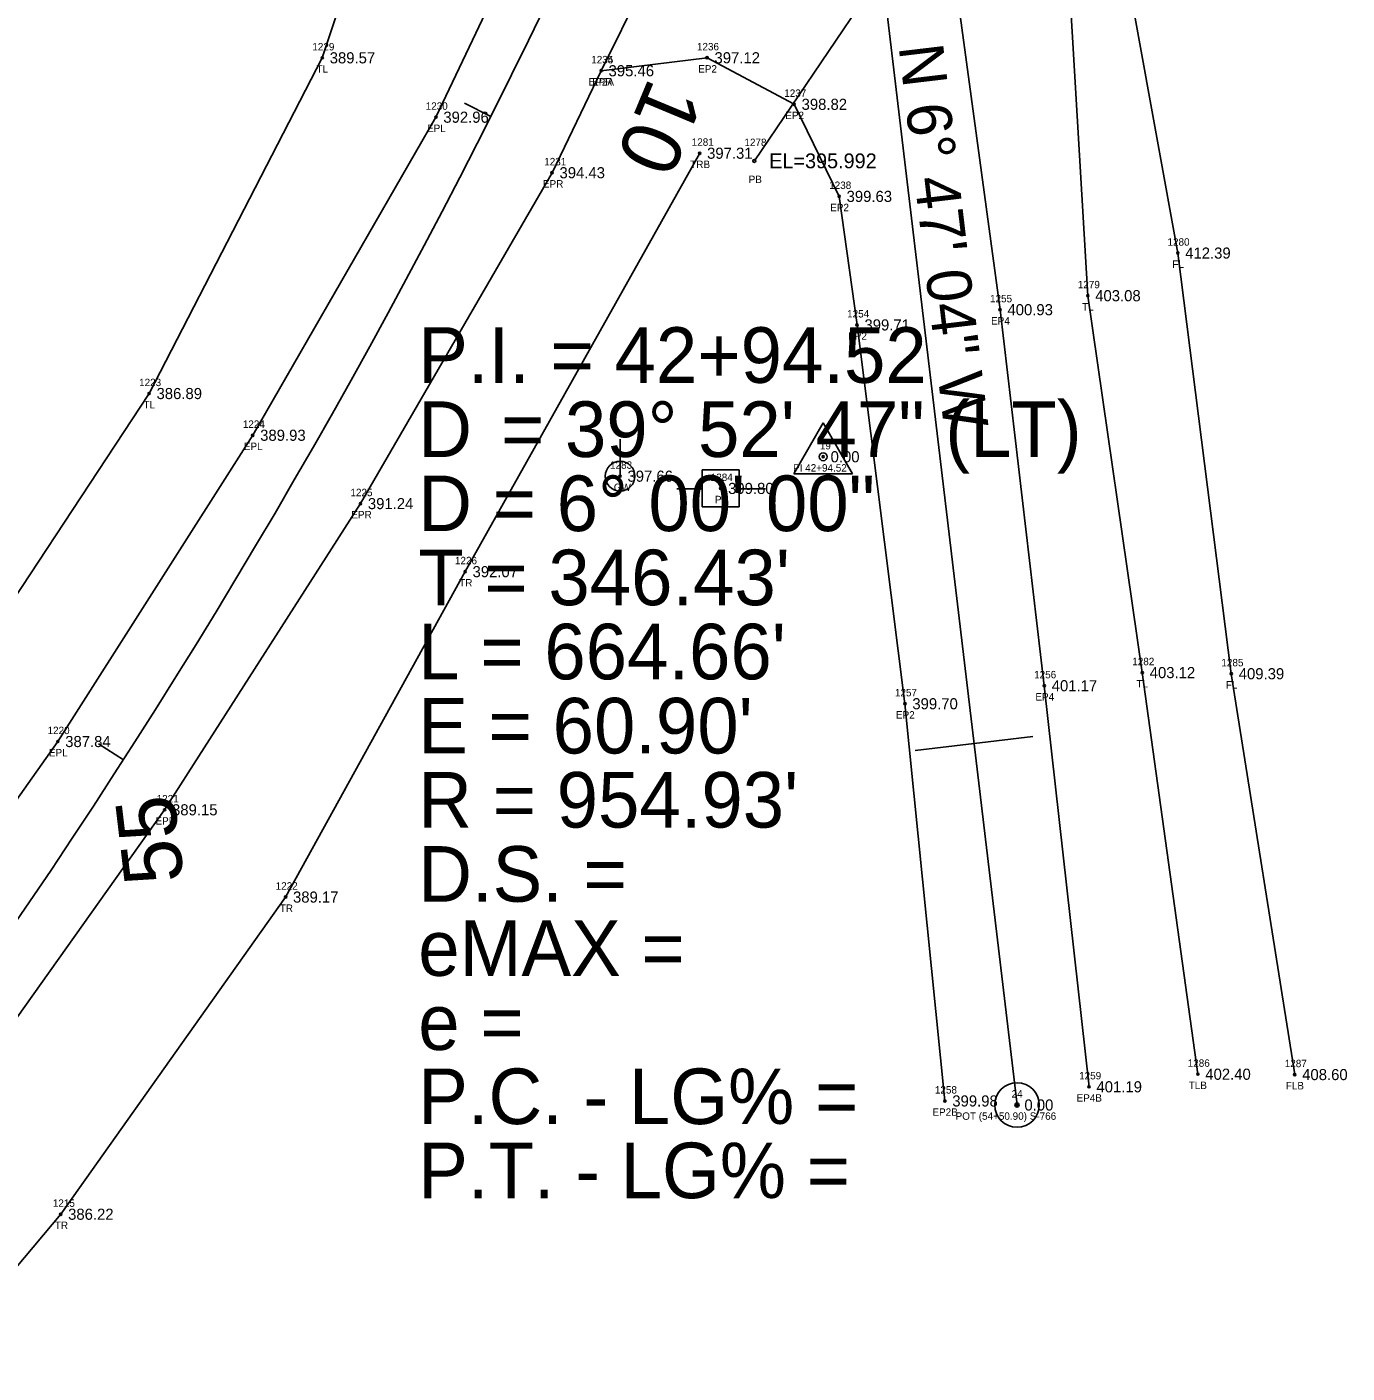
# Model space of a CAD drawing. Extents: x 2116015 to 2118228, y 979206 to 981145.
# Drawn here: x 2117886.2 to 2118064.3, y 980605.4 to 980787 of the extents above; entities that cross this region are included whole.
import ezdxf

# ---------------------------------------------------------------- set-up
doc = ezdxf.new("R2010")
doc.units = 0
for name, color, linetype in [('RD_EX_DR_Pipe', 7, 'Continuous'), ('RD_EX_DR_Pipe_txCode', 7, 'Continuous'), ('RD_EX_Fence_Other', 7, 'Continuous'), ('RD_EX_Fence_Other_txCode', 7, 'Continuous'), ('RD_EX_Road', 7, 'Continuous'), ('RD_EX_Road_txCode', 7, 'Continuous'), ('RD_EX_TX_Fence_Other_ELEV', 7, 'Continuous'), ('RD_EX_TX_Road_ELEV', 7, 'Continuous'), ('RD_EX_TX_UT_ELEV', 7, 'Continuous'), ('RD_EX_TX_VEG_ELEV', 7, 'Continuous'), ('RD_EX_UT', 7, 'Continuous'), ('RD_EX_UT_txCode', 7, 'Continuous'), ('RD_EX_VEG', 7, 'Continuous'), ('RD_EX_VEG_txCode', 7, 'Continuous'), ('RD_HC_Cl', 7, 'Continuous'), ('RD_HC_Data', 7, 'Continuous'), ('RD_HC_Data_Tic', 7, 'Continuous'), ('RD_HC_Survey_ELEV', 7, 'Continuous'), ('RD_HC_TX_Sta50', 7, 'Continuous'), ('RD_HC_txCode', 7, 'Continuous'), ('RD_SMD_Locator', 7, 'Continuous'), ('RD_TX_Pipe_ElevEX', 7, 'Continuous')]:
    doc.layers.add(name, color=color, linetype=linetype)

msp = doc.modelspace()

# ---------------------------------------------------------------- linework, layer by layer
at = {"layer": 'RD_EX_DR_Pipe'}
msp.add_line((2118018.48, 980819.47), (2117984.34, 980768.95), dxfattribs=at)
at = {"layer": 'RD_EX_Fence_Other'}
msp.add_lwpolyline([(2118035.7, 980855.33), (2118030.12, 980818.94), (2118041.46, 980756.51), (2118048.68, 980699.76), (2118057.24, 980645.68)], dxfattribs=at)
at = {"layer": 'RD_EX_Road'}
for points in [[(2117394.63, 980185.41), (2117388.45, 980192.75), (2117469.76, 980266.25), (2117487.02, 980282.1), (2117515.02, 980307.24), (2117543.53, 980333.04), (2117617.72, 980400.8), (2117691.88, 980468.07), (2117729.57, 980501.96), (2117798.93, 980572.83), (2117831.02, 980611), (2117861.69, 980650.07), (2117890.37, 980690.61), (2117916.67, 980731.93), (2117941.38, 980774.84), (2117963.75, 980821.95), (2117981.56, 980869.78), (2117996.2, 980917.73), (2118008.9, 980966.42), (2118019.55, 981015.46)], [(2117394.63, 980185.41), (2117401.85, 980177.36), (2117480.62, 980253.04), (2117556.27, 980319.95), (2117629.74, 980387.35), (2117703.2, 980454.29), (2117741.39, 980488.9), (2117777.53, 980523.58), (2117812.39, 980561.12), (2117844.66, 980599.64), (2117874.87, 980639.35), (2117904.78, 980681.4), (2117931.2, 980722.71), (2117957.05, 980767.35), (2117963.67, 980781.11), (2117980.28, 980814.62), (2117997.91, 980861.19), (2118015.62, 980912.37), (2118026.01, 980961.08), (2118037.02, 981011.88)], [(2118015.62, 980912.37), (2118010.99, 980870.98), (2118009.51, 980838.78), (2118009.44, 980820.82), (2118010.46, 980800.84), (2118017.48, 980748.87), (2118023.45, 980698.14), (2118029.49, 980644.03)], [(2117963.67, 980781.11), (2117977.96, 980782.86), (2117989.71, 980776.58), (2117995.78, 980764.16), (2117998.19, 980746.82), (2118004.65, 980695.71), (2118010.04, 980642.12)]]:
    msp.add_lwpolyline(points, dxfattribs=at)
at = {"layer": 'RD_EX_UT'}
for p, q in [((2117966.22, 980726.41), (2117966.22, 980731.41)), ((2117982.29, 980727.27), (2117977.29, 980727.27)), ((2117977.29, 980727.27), (2117977.29, 980722.27)), ((2117982.29, 980722.27), (2117982.29, 980727.27)), ((2117973.86, 980724.71), (2117977.33, 980724.71)), ((2117982.22, 980724.71), (2117985.86, 980724.71)), ((2117977.29, 980722.27), (2117982.29, 980722.27))]:
    msp.add_line(p, q, dxfattribs=at)
msp.add_circle((2117966.22, 980726.41), 2, dxfattribs=at)
at = {"layer": 'RD_EX_VEG'}
for points in [[(2117785.53, 980582.83), (2117819.37, 980618.82), (2117850.9, 980657.73), (2117876.27, 980697.46), (2117902.69, 980737.56), (2117926.05, 980782.85), (2117940.93, 980827.63), (2117963.69, 980874.19), (2117983.46, 980925.01), (2117981.09, 980973.08), (2118009.42, 981019.14)], [(2118029.75, 980856.49), (2118024.76, 980827.37), (2118029.32, 980750.76), (2118036.67, 980699.91), (2118044.17, 980645.73)], [(2117858.05, 980587.85), (2117890.76, 980626.84), (2117921.1, 980669.63), (2117945.32, 980713.53), (2117976.96, 980769.98)]]:
    msp.add_lwpolyline(points, dxfattribs=at)
at = {"layer": 'RD_HC_Cl'}
msp.add_line((2118019.77, 980641.58), (2117992.06, 980874.54), dxfattribs=at)
msp.add_arc((2117095.97, 981204.56), 954.93, 312.14821, 352.02781, dxfattribs=at)
at = {"layer": 'RD_HC_Data'}
for p, q in [((2117989.65, 980726.74), (2117993.62, 980733.62)), ((2117993.62, 980733.62), (2117997.59, 980726.74)), ((2117989.65, 980726.74), (2117997.59, 980726.74))]:
    msp.add_line(p, q, dxfattribs=at)
for centre, radius in [((2117993.62, 980729.03), 0.529), ((2118019.77, 980641.58), 3), ((2118019.77, 980641.58), 0.282)]:
    msp.add_circle(centre, radius, dxfattribs=at)
at = {"layer": 'RD_HC_Data_Tic'}
for p, q in [((2117948.8, 980774.94), (2117945.22, 980776.74)), ((2117899.22, 980688.14), (2117895.85, 980690.31)), ((2118013.97, 980690.34), (2118006.03, 980689.39)), ((2118013.97, 980690.34), (2118021.92, 980691.28))]:
    msp.add_line(p, q, dxfattribs=at)
at = {"layer": 'RD_SMD_Locator'}
for centre, radius in [((2117926.05, 980782.85), 0.15), ((2117977.96, 980782.86), 0.15), ((2117963.67, 980781.11), 0.15), ((2117963.67, 980781.11), 0.15), ((2117989.71, 980776.58), 0.15), ((2117941.38, 980774.84), 0.15), ((2117976.96, 980769.98), 0.15), ((2117984.34, 980768.95), 0.2), ((2117957.05, 980767.35), 0.15), ((2117995.78, 980764.16), 0.15), ((2118041.46, 980756.51), 0.15), ((2118029.32, 980750.76), 0.15), ((2118017.48, 980748.87), 0.15), ((2117998.19, 980746.82), 0.15), ((2117902.69, 980737.56), 0.15), ((2117916.67, 980731.93), 0.15), ((2117993.62, 980729.03), 0.15), ((2117966.22, 980726.41), 0.15), ((2117979.8, 980724.76), 0.15), ((2117931.2, 980722.71), 0.15), ((2117945.32, 980713.53), 0.15), ((2118036.67, 980699.91), 0.15), ((2118048.68, 980699.76), 0.15), ((2118023.45, 980698.14), 0.15), ((2118004.65, 980695.71), 0.15), ((2117890.37, 980690.61), 0.15), ((2117904.78, 980681.4), 0.15), ((2117921.1, 980669.63), 0.15), ((2118044.17, 980645.73), 0.15), ((2118057.24, 980645.68), 0.15), ((2118029.49, 980644.03), 0.15), ((2118010.04, 980642.12), 0.15), ((2118019.77, 980641.58), 0.15), ((2117890.76, 980626.84), 0.15)]:
    msp.add_circle(centre, radius, dxfattribs=at)

# ---------------------------------------------------------------- texts
at = {"layer": 'RD_EX_DR_Pipe_txCode'}
for s, p in [('1278', (2117983, 980770.95)), ('PB', (2117983.57, 980765.95))]:
    msp.add_text(s, height=1, dxfattribs=at).set_placement(p)
at = {"layer": 'RD_EX_Fence_Other_txCode'}
for s, p in [('1280', (2118040.07, 980757.51)), ('FL', (2118040.72, 980754.51)), ('1285', (2118047.34, 980700.76)), ('FL', (2118047.95, 980697.76)), ('1287', (2118055.89, 980646.68)), ('FLB', (2118056.03, 980643.68))]:
    msp.add_text(s, height=1, dxfattribs=at).set_placement(p)
at = {"layer": 'RD_EX_Road_txCode'}
for s, p in [('1236', (2117976.59, 980783.86)), ('1234', (2117962.33, 980782.11)), ('1235', (2117962.33, 980782.11)), ('EP2', (2117976.76, 980780.86)), ('EP2A', (2117961.98, 980779.11)), ('EPR', (2117962.45, 980779.11)), ('1237', (2117988.37, 980777.58)), ('1230', (2117940, 980775.84)), ('EP2', (2117988.51, 980774.58)), ('EPL', (2117940.18, 980772.84)), ('1231', (2117955.99, 980768.35)), ('EPR', (2117955.82, 980765.35)), ('1238', (2117994.43, 980765.16)), ('EP2', (2117994.57, 980762.16)), ('1255', (2118016.13, 980749.87)), ('1254', (2117996.85, 980747.82)), ('EP4', (2118016.27, 980746.87)), ('EP2', (2117996.99, 980744.82)), ('1224', (2117915.33, 980732.93)), ('EPL', (2117915.47, 980729.93)), ('1225', (2117929.85, 980723.71)), ('EPR', (2117929.97, 980720.71)), ('1256', (2118022.08, 980699.14)), ('1257', (2118003.3, 980696.71)), ('EP4', (2118022.25, 980696.14)), ('EP2', (2118003.44, 980693.71)), ('1220', (2117888.99, 980691.61)), ('EPL', (2117889.17, 980688.61)), ('1221', (2117903.71, 980682.4)), ('EPR', (2117903.55, 980679.4)), ('1259', (2118028.15, 980645.03)), ('1258', (2118008.69, 980643.12)), ('EP4B', (2118027.81, 980642.03)), ('EP2B', (2118008.36, 980640.12))]:
    msp.add_text(s, height=1, dxfattribs=at).set_placement(p)
at = {"layer": 'RD_EX_TX_Fence_Other_ELEV'}
for s, p in [('412.39', (2118042.46, 980755.76)), ('409.39', (2118049.68, 980699.01)), ('408.60', (2118058.24, 980644.93))]:
    msp.add_text(s, height=1.5, dxfattribs=at).set_placement(p)
at = {"layer": 'RD_EX_TX_Road_ELEV'}
for s, p in [('397.12', (2117978.96, 980782.11)), ('395.46', (2117964.67, 980780.36)), ('395.46', (2117964.67, 980780.36)), ('398.82', (2117990.71, 980775.83)), ('392.96', (2117942.38, 980774.09)), ('394.43', (2117958.05, 980766.6)), ('399.63', (2117996.78, 980763.41)), ('400.93', (2118018.48, 980748.12)), ('399.71', (2117999.19, 980746.07)), ('389.93', (2117917.67, 980731.18)), ('391.24', (2117932.2, 980721.96)), ('401.17', (2118024.45, 980697.39)), ('399.70', (2118005.65, 980694.96)), ('387.84', (2117891.37, 980689.86)), ('389.15', (2117905.78, 980680.65)), ('401.19', (2118030.49, 980643.28)), ('399.98', (2118011.04, 980641.37))]:
    msp.add_text(s, height=1.5, dxfattribs=at).set_placement(p)
at = {"layer": 'RD_EX_TX_UT_ELEV'}
msp.add_text('397.66', height=1.5, dxfattribs=at).set_placement((2117967.22, 980725.66))
at = {"layer": 'RD_EX_TX_VEG_ELEV'}
for s, p in [('389.57', (2117927.05, 980782.1)), ('397.31', (2117977.96, 980769.23)), ('403.08', (2118030.32, 980750.01)), ('386.89', (2117903.69, 980736.81)), ('392.07', (2117946.32, 980712.78)), ('403.12', (2118037.67, 980699.16)), ('389.17', (2117922.1, 980668.88)), ('402.40', (2118045.17, 980644.98)), ('386.22', (2117891.76, 980626.09))]:
    msp.add_text(s, height=1.5, dxfattribs=at).set_placement(p)
at = {"layer": 'RD_EX_UT_txCode'}
for s, p in [('1283', (2117964.87, 980727.41)), ('1284', (2117978.45, 980725.76)), ('GW', (2117965.38, 980724.41)), ('PP', (2117979.02, 980722.76))]:
    msp.add_text(s, height=1, dxfattribs=at).set_placement(p)
at = {"layer": 'RD_EX_VEG_txCode'}
for s, p in [('1229', (2117924.71, 980783.85)), ('TL', (2117925.28, 980780.85)), ('1281', (2117975.89, 980770.98)), ('TRB', (2117975.69, 980767.98)), ('1279', (2118027.97, 980751.76)), ('TL', (2118028.54, 980748.76)), ('1223', (2117901.34, 980738.56)), ('TL', (2117901.92, 980735.56)), ('1226', (2117943.95, 980714.53)), ('TR', (2117944.52, 980711.53)), ('1282', (2118035.32, 980700.91)), ('TL', (2118035.9, 980697.91)), ('1222', (2117919.76, 980670.63)), ('TR', (2117920.31, 980667.63)), ('1286', (2118042.8, 980646.73)), ('TLB', (2118042.93, 980643.73)), ('1215', (2117889.7, 980627.84)), ('TR', (2117889.97, 980624.84))]:
    msp.add_text(s, height=1, dxfattribs=at).set_placement(p)
at = {"layer": 'RD_HC_Data'}
msp.add_text('N 6%%d 47\' 04" W', height=6, rotation=276.7846, dxfattribs=at).set_placement((2118003.79, 980784.38))
for s, p in [('P.I. = 42+94.52', (2117939, 980739)), ('D', (2117939, 980729)), ('    = 39%%d 52\' 47" (LT)', (2117939, 980729)), ('D = 6%%d 00\' 00"', (2117939, 980719)), ("T = 346.43'", (2117939, 980709)), ("L = 664.66'", (2117939, 980699)), ("E = 60.90'", (2117939, 980689)), ("R = 954.93'", (2117939, 980679)), ('D.S. = ', (2117939, 980669)), ('eMAX = ', (2117939, 980659)), ('e = ', (2117939, 980649)), ('P.C. - LG% = ', (2117939, 980639)), ('P.T. - LG% = ', (2117939, 980629))]:
    msp.add_text(s, height=7.5, dxfattribs=at).set_placement(p)
at = {"layer": 'RD_HC_Survey_ELEV'}
for s, p in [('0.00', (2117994.62, 980728.28)), ('399.80', (2117980.8, 980724.01)), ('0.00', (2118020.77, 980640.83))]:
    msp.add_text(s, height=1.5, dxfattribs=at).set_placement(p)
at = {"layer": 'RD_HC_TX_Sta50'}
for s, rotation, p in [('10', 247.3733, (2117970.2, 980780.42)), ('55', 96.7846, (2117907.41, 980671.86))]:
    msp.add_text(s, height=8, rotation=rotation, dxfattribs=at).set_placement(p)
at = {"layer": 'RD_HC_txCode'}
for s, p in [('19', (2117993.17, 980730.03)), ('PI 42+94.52', (2117989.56, 980727.03)), ('24', (2118019.04, 980642.58)), ('POT (54+50.90) S-766', (2118011.49, 980639.58))]:
    msp.add_text(s, height=1, dxfattribs=at).set_placement(p)
at = {"layer": 'RD_TX_Pipe_ElevEX'}
msp.add_text('EL=395.992', height=2, dxfattribs=at).set_placement((2117986.34, 980767.95))

doc.saveas('drawing.dxf')
